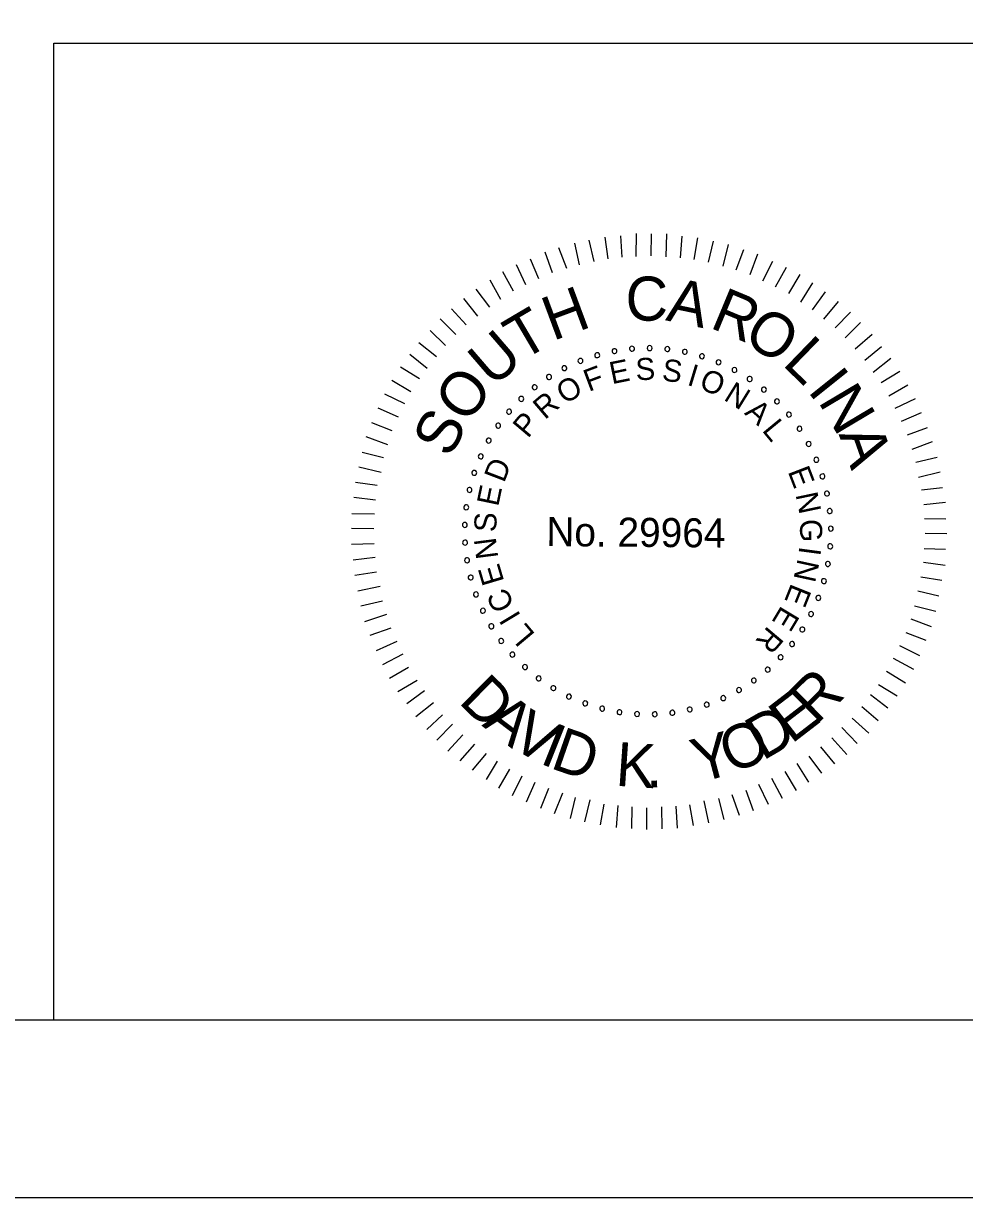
# Model space of a CAD drawing. Extents: x -125.5 to -89.4, y -5.1 to 16.9.
# Drawn here: x -102.985 to -100.333, y -5.066 to -1.761 of the extents above; entities that cross this region are included whole.
import ezdxf

# ---------------------------------------------------------------- set-up
doc = ezdxf.new("R2010")
doc.units = 0
for name, color, linetype in [('BR_BORDER LINES', 7, 'Continuous'), ('BR_TEXT', 7, 'Continuous'), ('Level 31', 7, 'Continuous')]:
    doc.layers.add(name, color=color, linetype=linetype)

msp = doc.modelspace()

# ---------------------------------------------------------------- linework, layer by layer
at = {"layer": 'BR_BORDER LINES'}
for p, q in [((-102.8989, -1.8161), (-97.5337, -1.8161)), ((-102.8989, -4.5661), (-102.8989, -1.8161)), ((-123.6994, -4.5662), (-90.0334, -4.5662))]:
    msp.add_line(p, q, dxfattribs=at)
at = {"layer": 'BR_TEXT'}
for p, q in [((-101.418, -2.4404), (-101.4312, -2.3793)), ((-101.3767, -2.4304), (-101.3908, -2.3711)), ((-101.3372, -2.423), (-101.3461, -2.362)), ((-101.2977, -2.419), (-101.3015, -2.3581)), ((-101.2582, -2.4168), (-101.2576, -2.3524)), ((-101.2161, -2.4146), (-101.2156, -2.3528)), ((-101.1741, -2.4175), (-101.1718, -2.3531)), ((-101.1338, -2.4204), (-101.129, -2.3595)), ((-101.0952, -2.425), (-101.0844, -2.3642)), ((-101.0549, -2.4331), (-101.0407, -2.374)), ((-101.4937, -2.4629), (-101.5147, -2.4044)), ((-101.4541, -2.4504), (-101.476, -2.3927)), ((-101.0138, -2.4437), (-100.9979, -2.3829)), ((-100.977, -2.4543), (-100.9551, -2.397)), ((-100.9376, -2.4675), (-100.9157, -2.4093)), ((-101.5695, -2.4966), (-101.5957, -2.4406)), ((-101.5325, -2.4798), (-101.556, -2.4238)), ((-100.9017, -2.485), (-100.8738, -2.4294)), ((-101.604, -2.5144), (-101.6344, -2.46)), ((-100.8658, -2.5024), (-100.8345, -2.4469)), ((-100.8282, -2.5208), (-100.796, -2.467)), ((-101.6704, -2.5593), (-101.7095, -2.5083)), ((-101.6394, -2.5381), (-101.6698, -2.4838)), ((-100.795, -2.5451), (-100.761, -2.4913)), ((-101.7041, -2.5847), (-101.744, -2.5346)), ((-100.7617, -2.5668), (-100.7252, -2.5165)), ((-100.7293, -2.5928), (-100.6886, -2.5434)), ((-101.7369, -2.6094), (-101.7786, -2.5644)), ((-100.6977, -2.618), (-100.6545, -2.5737)), ((-101.7663, -2.6366), (-101.8106, -2.5925)), ((-100.6697, -2.6456), (-100.6264, -2.6022)), ((-101.7958, -2.6673), (-101.8392, -2.6248)), ((-100.6416, -2.6768), (-100.594, -2.6351)), ((-101.8209, -2.6988), (-101.8704, -2.6598)), ((-100.6144, -2.7088), (-100.5677, -2.6705)), ((-101.8469, -2.732), (-101.8964, -2.6922)), ((-100.5906, -2.7424), (-100.5414, -2.7033)), ((-101.8686, -2.761), (-101.9224, -2.728)), ((-100.5686, -2.7718), (-100.516, -2.7396)), ((-101.893, -2.7977), (-101.9467, -2.7656)), ((-101.9104, -2.8319), (-101.9668, -2.804)), ((-100.5466, -2.8089), (-100.4931, -2.7776)), ((-100.5288, -2.8433), (-100.4711, -2.8164)), ((-101.9279, -2.8687), (-101.9851, -2.8433)), ((-100.5111, -2.8804), (-100.4542, -2.856)), ((-101.9454, -2.9072), (-102.0035, -2.8852)), ((-100.4943, -2.9192), (-100.4374, -2.8982)), ((-101.9577, -2.9474), (-102.0193, -2.9246)), ((-100.4809, -2.9596), (-100.4232, -2.9378)), ((-101.97, -2.9833), (-102.0308, -2.9682)), ((-100.4708, -2.9957), (-100.4107, -2.9816)), ((-101.9772, -3.0253), (-102.0397, -3.0094)), ((-100.4626, -3.0378), (-100.4024, -3.0229)), ((-101.9878, -3.0613), (-102.0487, -3.0531)), ((-100.4543, -3.074), (-100.3951, -3.0667)), ((-101.9925, -3.1024), (-102.0542, -3.0951)), ((-100.4478, -3.1152), (-100.3868, -3.1088)), ((-101.9954, -3.1419), (-102.0597, -3.1414)), ((-100.4464, -3.1547), (-100.3863, -3.1552)), ((-101.9974, -3.183), (-102.06, -3.1825)), ((-100.4442, -3.1959), (-100.3833, -3.1964)), ((-101.9961, -3.226), (-102.0604, -3.2272)), ((-100.4471, -3.2388), (-100.3871, -3.241)), ((-101.9938, -3.2646), (-102.0556, -3.2718)), ((-100.4492, -3.2774), (-100.3883, -3.2856)), ((-101.9898, -3.3058), (-102.0509, -3.3148)), ((-100.4563, -3.3185), (-100.3972, -3.3284)), ((-101.9799, -3.3454), (-102.0426, -3.3586)), ((-100.4653, -3.3579), (-100.4053, -3.3721)), ((-101.9733, -3.3875), (-102.0344, -3.4016)), ((-100.4742, -3.3999), (-100.4143, -3.415)), ((-101.9616, -3.4245), (-102.0236, -3.4454)), ((-100.4848, -3.4367), (-100.4275, -3.4586)), ((-101.95, -3.4632), (-102.0085, -3.4842)), ((-101.9331, -3.5003), (-101.9908, -3.5272)), ((-100.4989, -3.4752), (-100.4424, -3.4971)), ((-101.9162, -3.5364), (-101.9731, -3.566)), ((-100.5163, -3.512), (-100.4599, -3.5399)), ((-100.5346, -3.5479), (-100.4774, -3.5784)), ((-101.8994, -3.5735), (-101.9537, -3.6048)), ((-100.553, -3.5846), (-100.5, -3.6168)), ((-101.8756, -3.6106), (-101.93, -3.6419)), ((-100.5756, -3.6213), (-100.5235, -3.6535)), ((-101.8544, -3.6399), (-101.9045, -3.6764)), ((-100.5981, -3.6503), (-100.5495, -3.6876)), ((-101.829, -3.6736), (-101.8791, -3.7127)), ((-100.6224, -3.6836), (-100.5764, -3.7234)), ((-101.8043, -3.7073), (-101.8485, -3.7481)), ((-101.7754, -3.7333), (-101.8204, -3.7784)), ((-100.6502, -3.7168), (-100.6033, -3.7584)), ((-101.7465, -3.7636), (-101.7889, -3.8095)), ((-100.6787, -3.7424), (-100.6362, -3.7882)), ((-101.714, -3.7895), (-101.7548, -3.8364)), ((-100.7392, -3.7976), (-100.6993, -3.8452)), ((-100.7073, -3.7721), (-100.6648, -3.8188)), ((-101.6808, -3.8156), (-101.7207, -3.8633)), ((-100.772, -3.8231), (-100.7364, -3.8714)), ((-101.6501, -3.8373), (-101.6814, -3.8894)), ((-101.6151, -3.8599), (-101.6464, -3.9137)), ((-100.8393, -3.8663), (-100.808, -3.9206)), ((-100.8057, -3.8443), (-100.7727, -3.8969)), ((-101.5809, -3.8799), (-101.608, -3.9355)), ((-101.5442, -3.8974), (-101.5687, -3.953)), ((-100.8773, -3.8857), (-100.8468, -3.9418)), ((-101.5057, -3.9149), (-101.5276, -3.9713)), ((-101.4663, -3.9272), (-101.4891, -3.9854)), ((-100.9892, -3.9311), (-100.9682, -3.9897)), ((-100.9496, -3.9194), (-100.9286, -3.9763)), ((-100.9134, -3.9026), (-100.8865, -3.9586)), ((-101.4304, -3.9395), (-101.4446, -3.9986)), ((-101.3892, -3.9467), (-101.4044, -4.0084)), ((-101.3499, -3.9582), (-101.3598, -4.0165)), ((-101.3104, -3.9628), (-101.3152, -4.0246)), ((-101.271, -3.9657), (-101.2715, -4.0275)), ((-101.1869, -3.9664), (-101.1857, -4.0282)), ((-101.1465, -3.9642), (-101.1428, -4.026)), ((-101.1079, -3.9602), (-101.098, -4.0186)), ((-101.0674, -3.9494), (-101.0542, -4.0113)), ((-101.0262, -3.9429), (-101.0112, -4.0022)), ((-101.229, -3.9686), (-101.2295, -4.0296))]:
    msp.add_line(p, q, dxfattribs=at)
for centre, start, end in [((-101.3196, -2.6831), 10.6038, 190.6038), ((-101.2702, -2.6764), 5.0653, 185.0653), ((-101.2702, -2.6764), 185.0653, 5.0653), ((-101.2204, -2.6745), 359.5268, 179.5268), ((-101.2204, -2.6745), 179.5268, 359.5268), ((-101.1707, -2.6774), 173.9884, 353.9884), ((-101.1707, -2.6774), 353.9884, 173.9884), ((-101.4153, -2.7106), 21.6807, 201.6807), ((-101.4153, -2.7106), 201.6807, 21.6807), ((-101.3681, -2.6945), 16.1422, 196.1422), ((-101.3681, -2.6945), 196.1422, 16.1422), ((-101.3196, -2.6831), 190.6038, 10.6038), ((-101.1214, -2.6851), 168.4499, 348.4499), ((-101.1214, -2.6851), 348.4499, 168.4499), ((-101.0732, -2.6976), 162.9114, 342.9114), ((-101.0732, -2.6976), 342.9114, 162.9114), ((-101.0263, -2.7146), 337.373, 157.373), ((-101.4607, -2.7311), 27.2191, 207.2191), ((-101.4607, -2.7311), 207.2191, 27.2191), ((-101.0263, -2.7146), 157.373, 337.373), ((-100.9814, -2.736), 151.8345, 331.8345), ((-100.9814, -2.736), 331.8345, 151.8345), ((-101.5039, -2.7559), 32.7576, 212.7576), ((-101.5039, -2.7559), 212.7576, 32.7576), ((-100.9387, -2.7617), 146.2961, 326.2961), ((-100.9387, -2.7617), 326.2961, 146.2961), ((-101.5445, -2.7848), 38.2961, 218.2961), ((-101.5445, -2.7848), 218.2961, 38.2961), ((-100.8987, -2.7914), 140.7576, 320.7576), ((-100.8987, -2.7914), 320.7576, 140.7576), ((-101.5821, -2.8175), 43.8345, 223.8345), ((-101.5821, -2.8175), 223.8345, 43.8345), ((-100.8617, -2.8249), 135.2191, 315.2191), ((-100.8617, -2.8249), 315.2191, 135.2191), ((-101.6164, -2.8536), 49.373, 229.373), ((-101.6164, -2.8536), 229.373, 49.373), ((-100.8281, -2.8617), 129.6807, 309.6807), ((-100.8281, -2.8617), 309.6807, 129.6807), ((-101.6471, -2.8929), 54.9114, 234.9114), ((-101.6471, -2.8929), 234.9114, 54.9114), ((-100.7983, -2.9016), 124.1422, 304.1422), ((-100.7983, -2.9016), 304.1422, 124.1422), ((-101.6738, -2.935), 60.4499, 240.4499), ((-101.6738, -2.935), 240.4499, 60.4499), ((-100.7724, -2.9442), 118.6038, 298.6038), ((-100.7724, -2.9442), 298.6038, 118.6038), ((-101.6964, -2.9794), 65.9884, 245.9884), ((-101.6964, -2.9794), 245.9884, 65.9884), ((-100.7508, -2.9891), 113.0653, 293.0653), ((-100.7508, -2.9891), 293.0653, 113.0653), ((-101.7145, -3.0258), 71.5268, 251.5268), ((-101.7145, -3.0258), 251.5268, 71.5268), ((-100.7336, -3.0359), 107.5268, 287.5268), ((-100.7336, -3.0359), 287.5268, 107.5268), ((-101.7281, -3.0738), 77.0653, 257.0653), ((-101.7281, -3.0738), 257.0653, 77.0653), ((-100.721, -3.0841), 101.9884, 281.9884), ((-100.721, -3.0841), 281.9884, 101.9884), ((-101.737, -3.1228), 82.6038, 262.6038), ((-101.737, -3.1228), 262.6038, 82.6038), ((-100.7131, -3.1333), 96.4499, 276.4499), ((-100.7131, -3.1333), 276.4499, 96.4499), ((-101.7411, -3.1724), 88.1422, 268.1422), ((-101.7411, -3.1724), 268.1422, 88.1422), ((-100.71, -3.183), 90.9114, 270.9114), ((-100.71, -3.183), 270.9114, 90.9114), ((-101.7404, -3.2223), 93.6807, 273.6807), ((-101.7404, -3.2223), 273.6807, 93.6807), ((-100.7118, -3.2328), 85.373, 265.373), ((-100.7118, -3.2328), 265.373, 85.373), ((-101.7349, -3.2718), 99.2191, 279.2191), ((-101.7349, -3.2718), 279.2191, 99.2191), ((-100.7183, -3.2822), 79.8345, 259.8345), ((-100.7183, -3.2822), 259.8345, 79.8345), ((-101.7246, -3.3206), 104.7576, 284.7576), ((-101.7246, -3.3206), 284.7576, 104.7576), ((-100.7295, -3.3308), 74.2961, 254.2961), ((-100.7295, -3.3308), 254.2961, 74.2961), ((-101.7097, -3.3681), 110.2961, 290.2961), ((-101.7097, -3.3681), 290.2961, 110.2961), ((-100.7454, -3.378), 68.7576, 248.7576), ((-100.7454, -3.378), 248.7576, 68.7576), ((-101.6903, -3.414), 115.8345, 295.8345), ((-101.6903, -3.414), 295.8345, 115.8345), ((-100.7658, -3.4235), 63.2191, 243.2191), ((-100.7658, -3.4235), 243.2191, 63.2191), ((-101.6665, -3.4578), 121.373, 301.373), ((-101.6665, -3.4578), 301.373, 121.373), ((-100.7904, -3.4668), 57.6807, 237.6807), ((-100.7904, -3.4668), 237.6807, 57.6807), ((-101.6386, -3.4991), 126.9114, 306.9114), ((-101.6386, -3.4991), 306.9114, 126.9114), ((-100.8192, -3.5075), 52.1422, 232.1422), ((-100.8192, -3.5075), 232.1422, 52.1422), ((-101.6069, -3.5375), 132.4499, 312.4499), ((-101.6069, -3.5375), 312.4499, 132.4499), ((-101.5716, -3.5727), 137.9884, 317.9884), ((-101.5716, -3.5727), 317.9884, 137.9884), ((-100.8517, -3.5452), 46.6038, 226.6038), ((-100.8517, -3.5452), 226.6038, 46.6038), ((-101.5331, -3.6043), 143.5268, 323.5268), ((-101.5331, -3.6043), 323.5268, 143.5268), ((-100.8877, -3.5797), 41.0653, 221.0653), ((-100.8877, -3.5797), 221.0653, 41.0653), ((-101.4917, -3.632), 149.0653, 329.0653), ((-101.4917, -3.632), 329.0653, 149.0653), ((-100.9688, -3.6374), 29.9884, 209.9884), ((-100.9688, -3.6374), 209.9884, 29.9884), ((-100.9269, -3.6105), 35.5268, 215.5268), ((-100.9269, -3.6105), 215.5268, 35.5268), ((-101.4478, -3.6556), 154.6038, 334.6038), ((-101.4478, -3.6556), 334.6038, 154.6038), ((-101.4018, -3.6749), 340.1422, 160.1422), ((-101.0132, -3.6601), 24.4499, 204.4499), ((-101.0132, -3.6601), 204.4499, 24.4499), ((-101.4018, -3.6749), 160.1422, 340.1422), ((-101.3542, -3.6896), 165.6807, 345.6807), ((-101.3542, -3.6896), 345.6807, 165.6807), ((-101.3054, -3.6997), 351.2191, 171.2191), ((-101.3054, -3.6997), 171.2191, 351.2191), ((-101.2559, -3.705), 356.7576, 176.7576), ((-101.2061, -3.7055), 2.2961, 182.2961), ((-101.1564, -3.7012), 7.8345, 187.8345), ((-101.1564, -3.7012), 187.8345, 7.8345), ((-101.1074, -3.6921), 13.373, 193.373), ((-101.1074, -3.6921), 193.373, 13.373), ((-101.0595, -3.6784), 18.9114, 198.9114), ((-101.0595, -3.6784), 198.9114, 18.9114), ((-101.2559, -3.705), 176.7576, 356.7576), ((-101.2061, -3.7055), 182.2961, 2.2961)]:
    msp.add_arc(centre, 0.00701, start, end, dxfattribs=at)
at = {"layer": 'Level 31'}
msp.add_lwpolyline([(-125.5328, -5.0661), (-89.5328, -5.0661), (-89.5328, 16.9339), (-125.5328, 16.9339)], close=True, dxfattribs=at)

# ---------------------------------------------------------------- texts
at = {"layer": 'BR_TEXT'}
for s, height, rotation, p in [('C', 0.1241, 359.5482, (-101.2889, -2.5969)), ('H', 0.1241, 20.3637, (-101.4933, -2.6552)), ('A', 0.1241, 348.1981, (-101.1775, -2.5961)), ('R', 0.1241, 337.4344, (-101.0542, -2.616)), ('T', 0.1241, 30.4992, (-101.5812, -2.7128)), ('O', 0.1239, 326.5869, (-100.962, -2.6528)), ('U', 0.1241, 40.8022, (-101.6624, -2.7875)), ('L', 0.1241, 315.9488, (-100.8494, -2.7205)), ('E', 0.0622, 11.4103, (-101.3269, -2.7764)), ('S', 0.0622, 2.208, (-101.2591, -2.7654)), ('S', 0.0622, 352.6608, (-101.1878, -2.7657)), ('O', 0.1241, 52.0267, (-101.7369, -2.8914)), ('F', 0.0622, 20.6127, (-101.392, -2.7981)), ('I', 0.0622, 343.1136, (-101.1175, -2.7777)), ('O', 0.0622, 338.4392, (-101.0841, -2.7878)), ('I', 0.1241, 308.6613, (-100.778, -2.7948)), ('O', 0.0622, 30.8477, (-101.4594, -2.8341)), ('N', 0.0622, 328.2042, (-101.0145, -2.8192)), ('N', 0.1241, 300.7037, (-100.7474, -2.8242)), ('R', 0.0622, 40.3949, (-101.5156, -2.878)), ('A', 0.0622, 318.657, (-100.9555, -2.8592)), ('S', 0.1239, 63.2511, (-101.7823, -2.9871)), ('P', 0.0622, 49.9421, (-101.5636, -2.9306)), ('L', 0.0622, 309.4546, (-100.9057, -2.9066)), ('A', 0.1241, 289.4792, (-100.6882, -2.9172)), ('D', 0.0622, 69.0364, (-101.6306, -3.0559)), ('E', 0.0622, 291.049, (-100.8319, -3.0219)), ('E', 0.0622, 78.2388, (-101.6472, -3.1226)), ('N', 0.0622, 281.8466, (-100.8097, -3.0869)), ('S', 0.0622, 87.786, (-101.6529, -3.1936)), ('No. 29964', 0.08175, 359.5268, (-101.5117, -3.232)), ('G', 0.0622, 272.2995, (-100.7979, -3.1572)), ('N', 0.0622, 97.3332, (-101.6467, -3.2646)), ('I', 0.0622, 262.4084, (-100.7983, -3.231)), ('N', 0.0622, 257.7339, (-100.8028, -3.2656)), ('E', 0.0622, 106.5355, (-101.6297, -3.3312)), ('C', 0.0622, 116.4266, (-101.5998, -3.3987)), ('E', 0.0622, 248.1867, (-100.8209, -3.3346)), ('E', 0.0622, 238.9844, (-100.8488, -3.3973)), ('I', 0.0622, 121.1011, (-101.5818, -3.4285)), ('L', 0.0622, 129.9595, (-101.5411, -3.4807)), ('R', 0.0622, 229.782, (-100.8865, -3.4548)), ('D', 0.1236, 315.4053, (-101.7616, -3.6713)), ('R', 0.1236, 44.5947, (-100.7507, -3.7369)), ('E', 0.1236, 37.5339, (-100.8213, -3.7908)), ('A', 0.1236, 322.8377, (-101.695, -3.737)), ('V', 0.1236, 330.5179, (-101.6178, -3.7952)), ('D', 0.1236, 30.1015, (-100.9022, -3.8377)), ('I', 0.1236, 338.1981, (-101.5336, -3.8425)), ('O', 0.1236, 22.4212, (-100.9915, -3.8748)), ('D', 0.1236, 340.7995, (-101.5037, -3.856)), ('Y', 0.1236, 14.8649, (-101.0833, -3.8993)), ('K', 0.1236, 356.098, (-101.3185, -3.9065)), ('.', 0.1236, 3.1588, (-101.2299, -3.9128))]:
    msp.add_text(s, height=height, rotation=rotation, dxfattribs=at).set_placement(p)

doc.saveas('drawing.dxf')
